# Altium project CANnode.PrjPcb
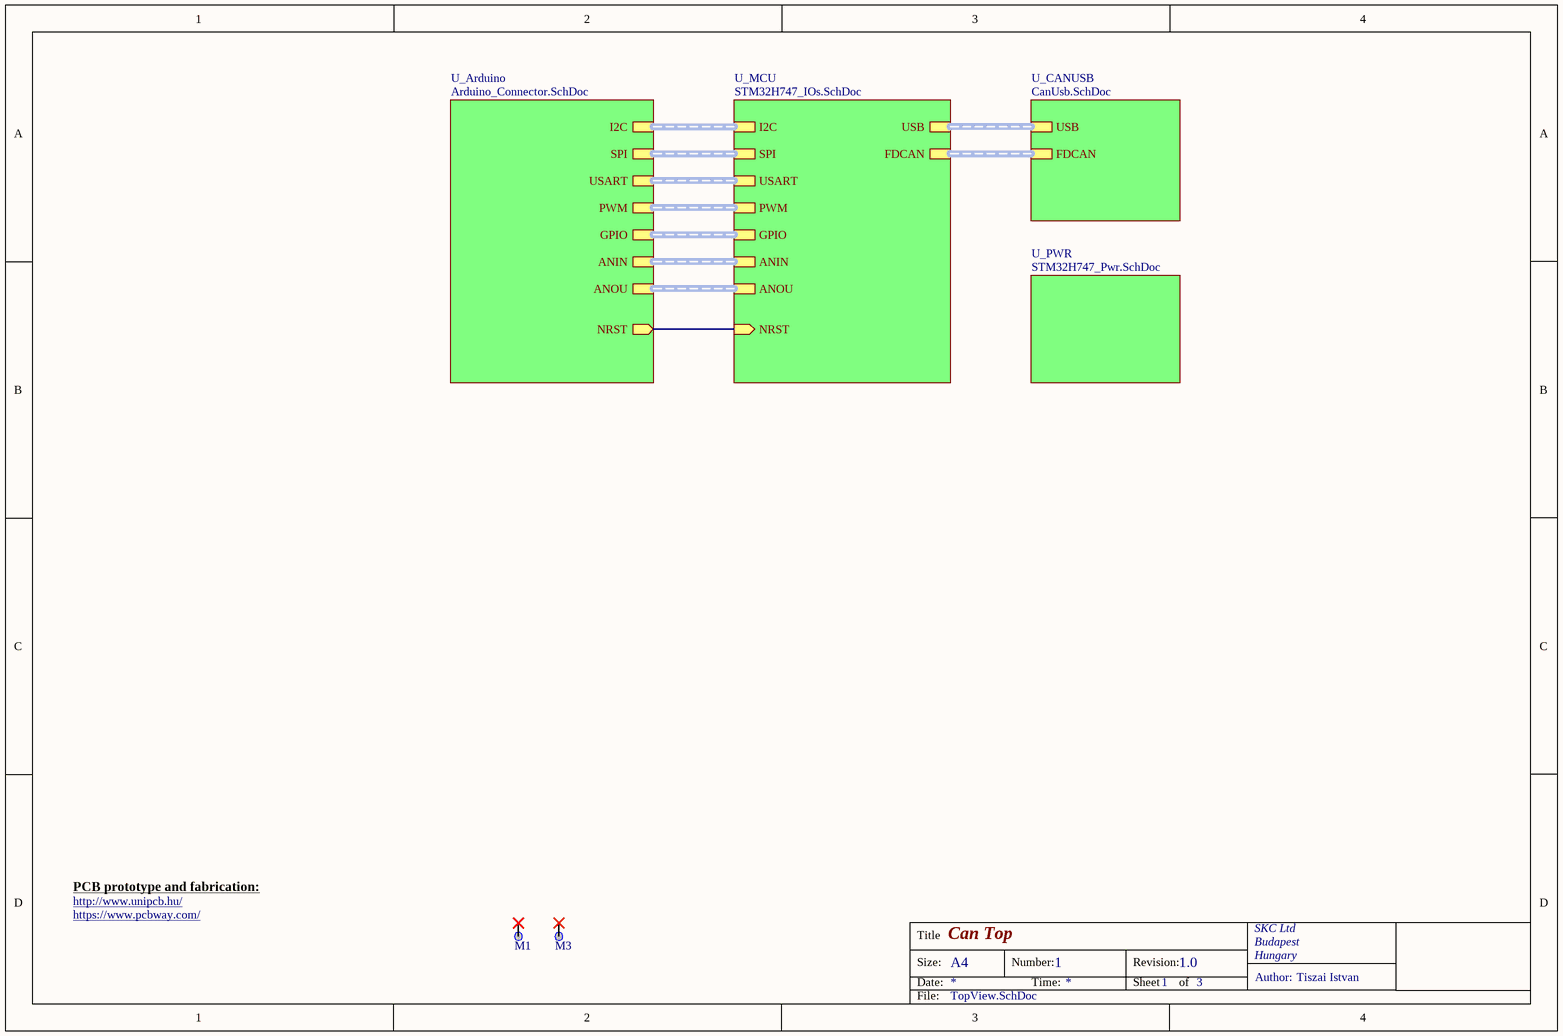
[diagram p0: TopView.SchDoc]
5 sheets, 99 parts. Net scope: hierarchical (ports join the sheet entries above them; power ports are global).
Board file: CANnode.PcbDoc
Sheets:
  TopView.SchDoc
    U_MCU = STM32H747_IOs.SchDoc
    U_PWR = STM32H747_Pwr.SchDoc
    U_CANUSB = CanUsb.SchDoc
    U_Arduino = Arduino_Connector.SchDoc

## Sheet TopView.SchDoc: Can Top
size A4; Author: Tiszai Istvan; Organization: SKC Ltd; Address1: Budapest; Address2: Hungary; DocumentNumber: 1; Revision: 1.0; SheetNumber: 1; SheetTotal: 3

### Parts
M1  (no value)  [Keystone 614]  (no BOM)
M3  (no value)  [Keystone 614]  (no BOM)

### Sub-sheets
U_Arduino = Arduino_Connector.SchDoc: I2C (harness I2C), SPI (harness SPI), USART (harness USART), PWM (harness PWM), GPIO (harness GPIO), ANIN (harness ANIN), ANOU (harness ANOU), NRST (out)
U_CANUSB = CanUsb.SchDoc: USB (harness USB), FDCAN (harness FDCAN)
U_MCU = STM32H747_IOs.SchDoc: NRST (in), USB (harness USB), FDCAN (harness FDCAN), I2C (harness I2C), SPI (harness SPI), USART (harness USART), PWM (harness PWM), GPIO (harness GPIO), ANIN (harness ANIN), ANOU (harness ANOU)
U_PWR = STM32H747_Pwr.SchDoc: no entries

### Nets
NRST: sheet U_MCU/NRST, sheet U_Arduino/NRST

Not connected (* = marked no-connect by the designer): M1 1*; M3 1*

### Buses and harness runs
harness sheet U_Arduino/ANIN = sheet U_MCU/ANIN
harness sheet U_Arduino/ANOU = sheet U_MCU/ANOU
harness sheet U_Arduino/GPIO = sheet U_MCU/GPIO
harness sheet U_Arduino/I2C = sheet U_MCU/I2C
harness sheet U_Arduino/PWM = sheet U_MCU/PWM
harness sheet U_Arduino/SPI = sheet U_MCU/SPI
harness sheet U_Arduino/USART = sheet U_MCU/USART
harness sheet U_CANUSB/FDCAN = sheet U_MCU/FDCAN
harness sheet U_CANUSB/USB = sheet U_MCU/USB

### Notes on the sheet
- http://www.unipcb.hu/
- https://www.pcbway.com/
- PCB prototype and fabrication:

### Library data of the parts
M1 M3 = TP: TAVTARTO

## Sheet STM32H747_IOs.SchDoc: Can STM32H747 IOs
size A4; Author: Tiszai Istvan; CompanyName: SKC Ltd; Engineer: Tiszai Istvan; Organization: SKC Ltd; Address1: Budapest; Address2: Hungary; DocumentNumber: 1; Revision: 1.0; SheetNumber: 2; SheetTotal: 3; FileName: STM32H747_IOs.SchDoc
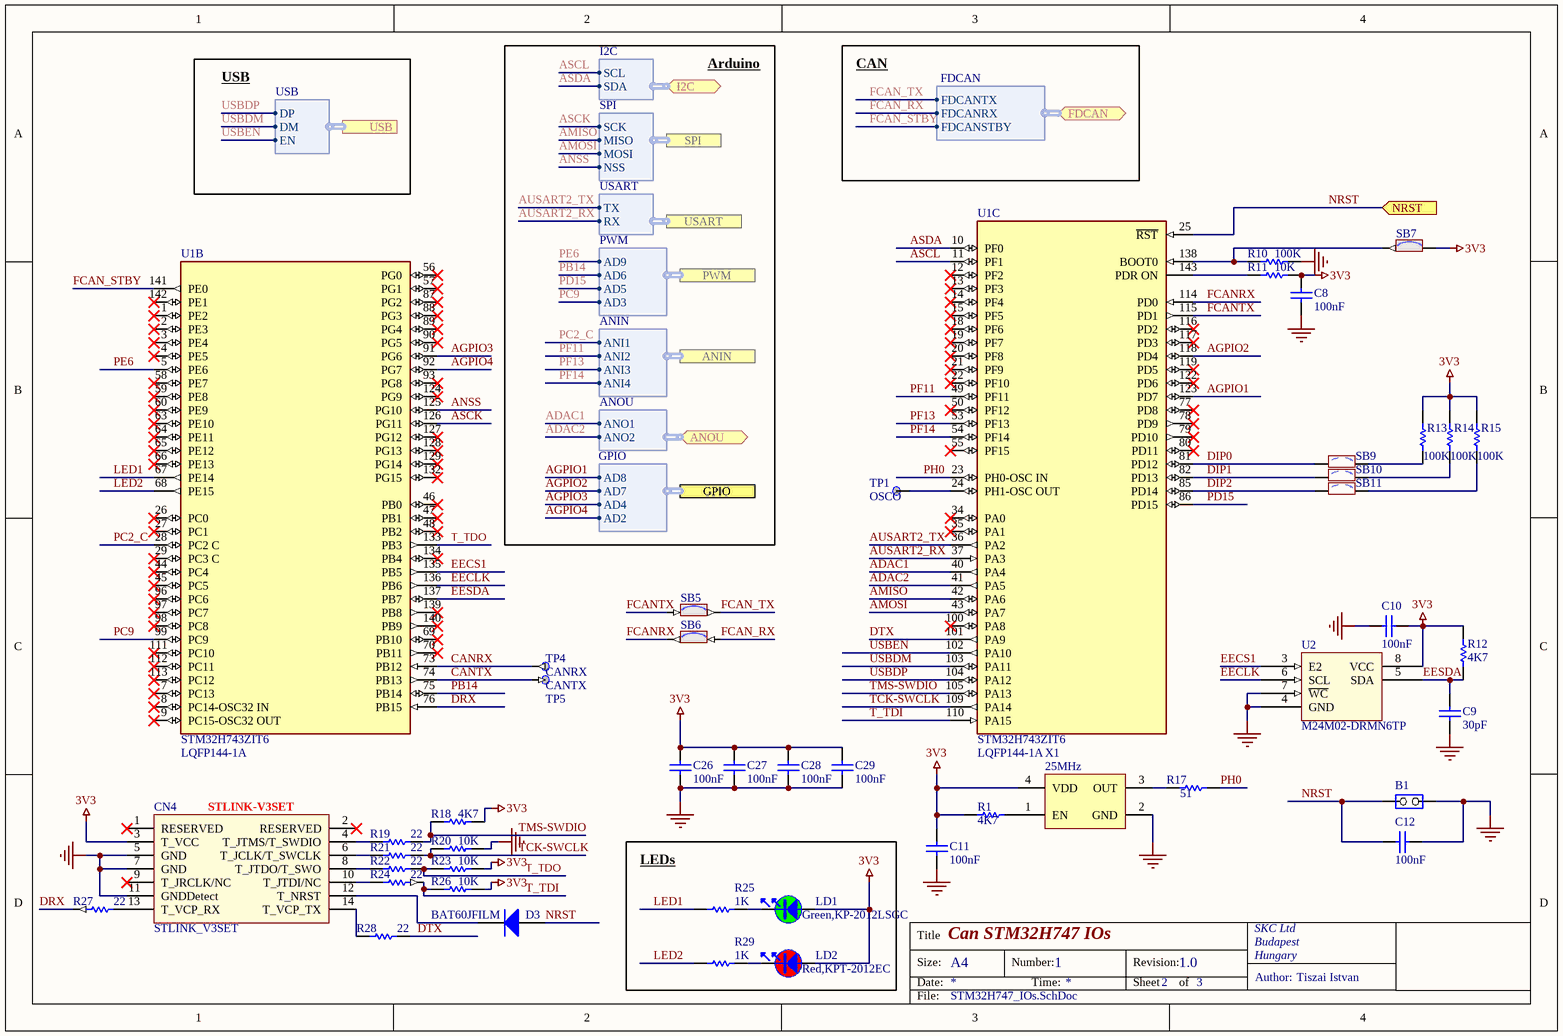
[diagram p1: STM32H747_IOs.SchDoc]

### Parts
B1  berg2  [SIP2/2.54]  (value not drawn)
C8  100nF  [0603]
C9  30pF  [0603]
C10  100nF  [0603]
C11  100nF  [0603]
C12  100nF  [0603]
C26  100nF  [0603]
C27  100nF  [0603]
C28  100nF  [0603]
C29  100nF  [0603]
CN4  STLINK_V3SET  [HDR2X7--50mil]
D3  BAT60JFILM  [SOD-323]
LD1  value Green,KP-2012LSGC  [LED 0805/2012 GREEN]  (hidden comment: LED_green)
LD2  value Red,KPT-2012EC  [LED 0805/2012 RED]  (hidden comment: LED_red)
R1  4K7  [0603]
R10  100K  [0603]
R11  10K  [0603]
R12  4K7  [0603]
R13  100K  [0603]
R14  100K  [0603]
R15  100K  [0603]
R17  value 51  [0603]  (hidden comment: 51R)
R18  4K7  [0603]
R19  22  [0603]
R20  10K  [0603]
R21  22  [0603]
R22  22  [0603]
R23  10K  [0603]
R24  22  [0603]
R25  1K  [0603]
R26  10K  [0603]
R27  22  [0603]
R28  22  [0603]
R29  1K  [0603]
SB5  SB_ON  [sb0603]  (value not drawn)
SB6  SB_ON  [sb0603]  (value not drawn)
SB7  SB_ON  [sb0603]  (value not drawn)
SB9  SB_OFF  [SB0603]  (value not drawn)
SB10  SB_OFF  [SB0603]  (value not drawn)
SB11  SB_OFF  [SB0603]  (value not drawn)
TP1  OSCO  [Through Hole Pad]
TP4  CANRX  [Through Hole Pad]
TP5  CANTX  [Through Hole Pad]
U1  STM32H743ZIT6  Package: LQFP144-1A  [FP-LQFP144-1A-IPC_B]  (parts B,C of 3)
U2  M24M02-DRMN6TP  [SOIC-8]
X1  value 25MHz  [OSC_NDK]  (hidden comment: Oscillator_4pins)

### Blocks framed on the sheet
LEDs: LD1 LD2 R25 R29

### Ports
ANIN (harness ANIN), ANOU (bidir, harness ANOU), FDCAN (bidir, harness FDCAN), GPIO (harness GPIO), I2C (bidir, harness I2C), NRST (in), PWM (harness PWM), SPI (harness SPI), USART (harness USART), USB (harness USB)

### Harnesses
FDCAN: FDCANTX, FDCANRX, FDCANSTBY
USB: EN, DM, DP
I2C: SCL, SDA
SPI: MISO, SCK, MOSI, NSS
USART: RX, TX
PWM: AD6, AD9, AD5, AD3
ANIN: ANI2, ANI1, ANI3, ANI4
ANOU: ANO1, ANO2
GPIO: AD7, AD8, AD4, AD2

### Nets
3V3: C8.2 C10.1 C11.2 C26.2 C27.2 C28.2 C29.2 CN4.3(T_VCC) LD1.1 LD2.1 R1.2 R11.1 R12.1 R13.1 R14.1 R15.1 R18.1 R23.1 R26.1 SB7.2 U2.8(VCC) X1.4(VDD)
GND: B1.1(COMMON) C8.1 C9.1 C10.2 C11.1 C12.1 C26.1 C27.1 C28.1 C29.1 CN4.5(GND) CN4.7(GND) CN4.11(GNDDetect) R10.1 R20.1 U2.4(GND) U2.7(~{WC}) X1.2(GND)
ADAC1: U1.40(PA4) ; port ANOU.ANO1
ADAC2: U1.41(PA5) ; port ANOU.ANO2
AGPIO1: U1.123(PD7) ; port GPIO.AD8
AGPIO2: U1.118(PD4) ; port GPIO.AD7
AGPIO3: U1.91(PG6) ; port GPIO.AD4
AGPIO4: U1.92(PG7) ; port GPIO.AD2
AMISO: U1.42(PA6) ; port SPI.MISO
AMOSI: U1.43(PA7) ; port SPI.MOSI
ANSS: U1.125(PG10) ; port SPI.NSS
ASCK: U1.126(PG11) ; port SPI.SCK
ASCL: U1.11(PF1) ; port I2C.SCL
ASDA: U1.10(PF0) ; port I2C.SDA
AUSART2_RX: U1.37(PA3) ; port USART.RX
AUSART2_TX: U1.36(PA2) ; port USART.TX
CANRX: TP4.1 U1.73(PB12)
CANTX: TP5.1 U1.74(PB13)
DIP0: SB9.1 U1.81(PD12)
DIP1: SB10.1 U1.82(PD13)
DIP2: SB11.1 U1.85(PD14)
DRX: R27.1 U1.76(PB15)
DTX: R28.2 U1.101(PA9)
EECLK: U1.136(PB6) U2.6(SCL)
EECS1: U1.135(PB5) U2.3(E2)
EESDA: C9.2 R12.2 U1.137(PB7) U2.5(SDA)
FCAN_RX: SB6.2 ; port FDCAN.FDCANRX
FCAN_STBY: U1.141(PE0) ; port FDCAN.FDCANSTBY
FCAN_TX: SB5.2 ; port FDCAN.FDCANTX
FCANRX: SB6.1 U1.114(PD0)
FCANTX: SB5.1 U1.115(PD1)
LED1: R25.1 U1.67(PE14)
LED2: R29.1 U1.68(PE15)
NRST: B1.2(NO) C12.2 D3.1(A) U1.25(~{RST}) ; port NRST
PB14: U1.75(PB14) ; port PWM.AD6
PC2_C: U1.28(PC2_C) ; port ANIN.ANI1
PC9: U1.99(PC9) ; port PWM.AD3
PD15: U1.86(PD15) ; port PWM.AD5
PE6: U1.5(PE6) ; port PWM.AD9
PF11: U1.49(PF11) ; port ANIN.ANI2
PF13: U1.53(PF13) ; port ANIN.ANI3
PF14: U1.54(PF14) ; port ANIN.ANI4
PH0: R17.2 U1.23(PH0-OSC_IN)
T_TDI: R24.2 R26.2 U1.110(PA15)
T_TDO: R22.2 R23.2 U1.133(PB3)
TCK-SWCLK: R20.2 R21.2 U1.109(PA14)
TMS-SWDIO: R18.2 R19.2 U1.105(PA13)
USBDM: U1.103(PA11) ; port USB.DM
USBDP: U1.104(PA12) ; port USB.DP
USBEN: U1.102(PA10) ; port USB.EN
NetCN4_4: CN4.4(T_JTMS/T_SWDIO) R19.1
NetCN4_6: CN4.6(T_JCLK/T_SWCLK) R21.1
NetCN4_8: CN4.8(T_JTDO/T_SWO) R22.1
NetCN4_10: CN4.10(T_JTDI/NC) R24.1
NetCN4_12: CN4.12(T_NRST) D3.2(K)
NetCN4_13: CN4.13(T_VCP_RX) R27.2
NetCN4_14: CN4.14(T_VCP_TX) R28.1
NetLD1_2: LD1.2 R25.2
NetLD2_2: LD2.2 R29.2
NetR1_1: R1.1 X1.1(EN)
NetR10_2: R10.2 SB7.1 U1.138(BOOT0)
NetR11_2: R11.2 U1.143(PDR_ON)
NetR13_2: R13.2 SB9.2
NetR14_2: R14.2 SB10.2
NetR15_2: R15.2 SB11.2
NetR17_1: R17.1 X1.3(OUT)
NetTP1_1: TP1.1 U1.24(PH1-OSC_OUT)

Not connected (* = marked no-connect by the designer): CN4 1(RESERVED)* 2(RESERVED)* 9(T_JRCLK/NC)*; U1 1(PE2)* 2(PE3)* 3(PE4)* 4(PE5)* 7(PC13)* 8(PC14-OSC32_IN)* 9(PC15-OSC32_OUT)* 12(PF2)* 13(PF3)* 14(PF4)* 15(PF5)* 18(PF6)* 19(PF7)* 20(PF8)* 21(PF9)* 22(PF10)* 26(PC0)* 27(PC1)* 29(PC3_C)* 34(PA0)* 35(PA1)* 44(PC4)* 45(PC5)* 46(PB0)* 47(PB1)* 48(PB2)* 50(PF12)* 55(PF15)* 56(PG0)* 57(PG1)* 58(PE7)* 59(PE8)* 60(PE9)* 63(PE10)* 64(PE11)* 65(PE12)* 66(PE13)* 69(PB10)* 70(PB11)* 77(PD8)* 78(PD9)* 79(PD10)* 80(PD11)* 87(PG2)* 88(PG3)* 89(PG4)* 90(PG5)* 93(PG8)* 96(PC6)* 97(PC7)* 98(PC8)* 100(PA8)* 111(PC10)* 112(PC11)* 113(PC12)* 116(PD2)* 117(PD3)* 119(PD5)* 122(PD6)* 124(PG9)* 127(PG12)* 128(PG13)* 129(PG14)* 132(PG15)* 134(PB4)* 139(PB8)* 140(PB9)* 142(PE1)*; U2 1(NC) 2(NC)

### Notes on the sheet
- USB
- Arduino
- CAN
- (near CN4) STLINK-V3SET

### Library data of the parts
B1 = JP2: berg 2 pin
C8 C10 C11 C26-C29 = MCD-00102: Capacitor, MLCC, 100nF, 25V, X7R, 10%, 0603
C9 = MCD-00102: Capacitor, MLCC, 30pF, 250V, 5%
C12 = CAP: Capacitor, MLCC, 100nF, 25V, X7R, 10%, 0603
CN4 = STLINK_V3SET: STLINK-V3SET -  Programmer / Debugger
D3 = Diode: Small Signal Schottky Diode, Single, 10 V, 3 A, 580 mV, 5 A
LD1 = MCD-00050: LED, Low Power, Green, SMD, 0805 2 mA,
LD2 = MCD-00049: LED, Low Power, High Efficiency Red, SMD, 0805 , 30 mA
R1 = MCD-00053: Resistor,,5%
R10 R12-R15 R18 R23 R26 = MCD-00053: Resistor,5%
R11 = MCD-00053: Resistor, 5%,
R17 = MCD-00485: Resistor,1%,
R19 = Resistor_ST: Resistor, 22, 1%
R20 = MCD-00053: Resistor,10K,5%
R21 R22 R24 R27 R28 = Resistor_ST: Resistor 22, 1%
R25 = MCD-00225: Resistor,1K,1%
R29 = MCD-00507: Resistor,1K,1%,
SB5-SB7 = MCD-00071: Solder Bridge ON; Part_Type: Mechanical; Provided_By: Subcon; Initial_Board_Reference: mb1274
SB9-SB11 = MCD-00072: Solder Bridge OFF; Part_Type: Mechanical; Initial_Board_Reference: mb1274
TP1 TP4 TP5 = TP
U1 = CMP-12105-000003-1: IC MCU 32BIT 2MB FLASH 144LQFP; Manufacturer: STMicroelectronics; Number Of I2C Channels: 4; Number Of A/D Converters: 2; Standoff Height: 0.05mm; Interface: I2C,SPI,UART,USART,EBI/EMI,CAN,USB,LIN,IrDA,Other; Max Supply Voltage: 3.6V; Number Of Adc Channels: 36; Ram Size: 1MBytes; Number Of Cores: 1; Frequency: 400MHz; Data Bus Width: 32bits; Core Architecture: ARM Cortex-M7; Memory Size: 2MBytes; Number Of Timers/Counters: 22; Min Supply Voltage: 1.62V; Number Of Spi Channels: 6; Max Junction Temp: +125°C; Number Of I/Os: 114
U2 = M24M02-DRMN6TP: 2-Mbit serial I²C bus EEPROM
X1 = MCD-00597: Oscillator, 25 MHz, 50 ppm, SMD, 3.2mm x 2.5mm, CMOS, 3.3 V

## Sheet STM32H747_Pwr.SchDoc: Can STM32H747 Power
size A4; Author: Tiszai Istvan; CompanyName: SKC Ltd; Organization: GreenLab Ltd; Address1: Budapest; Address2: Hungary; DocumentNumber: 1; Revision: 1.0; SheetNumber: 3; SheetTotal: 3
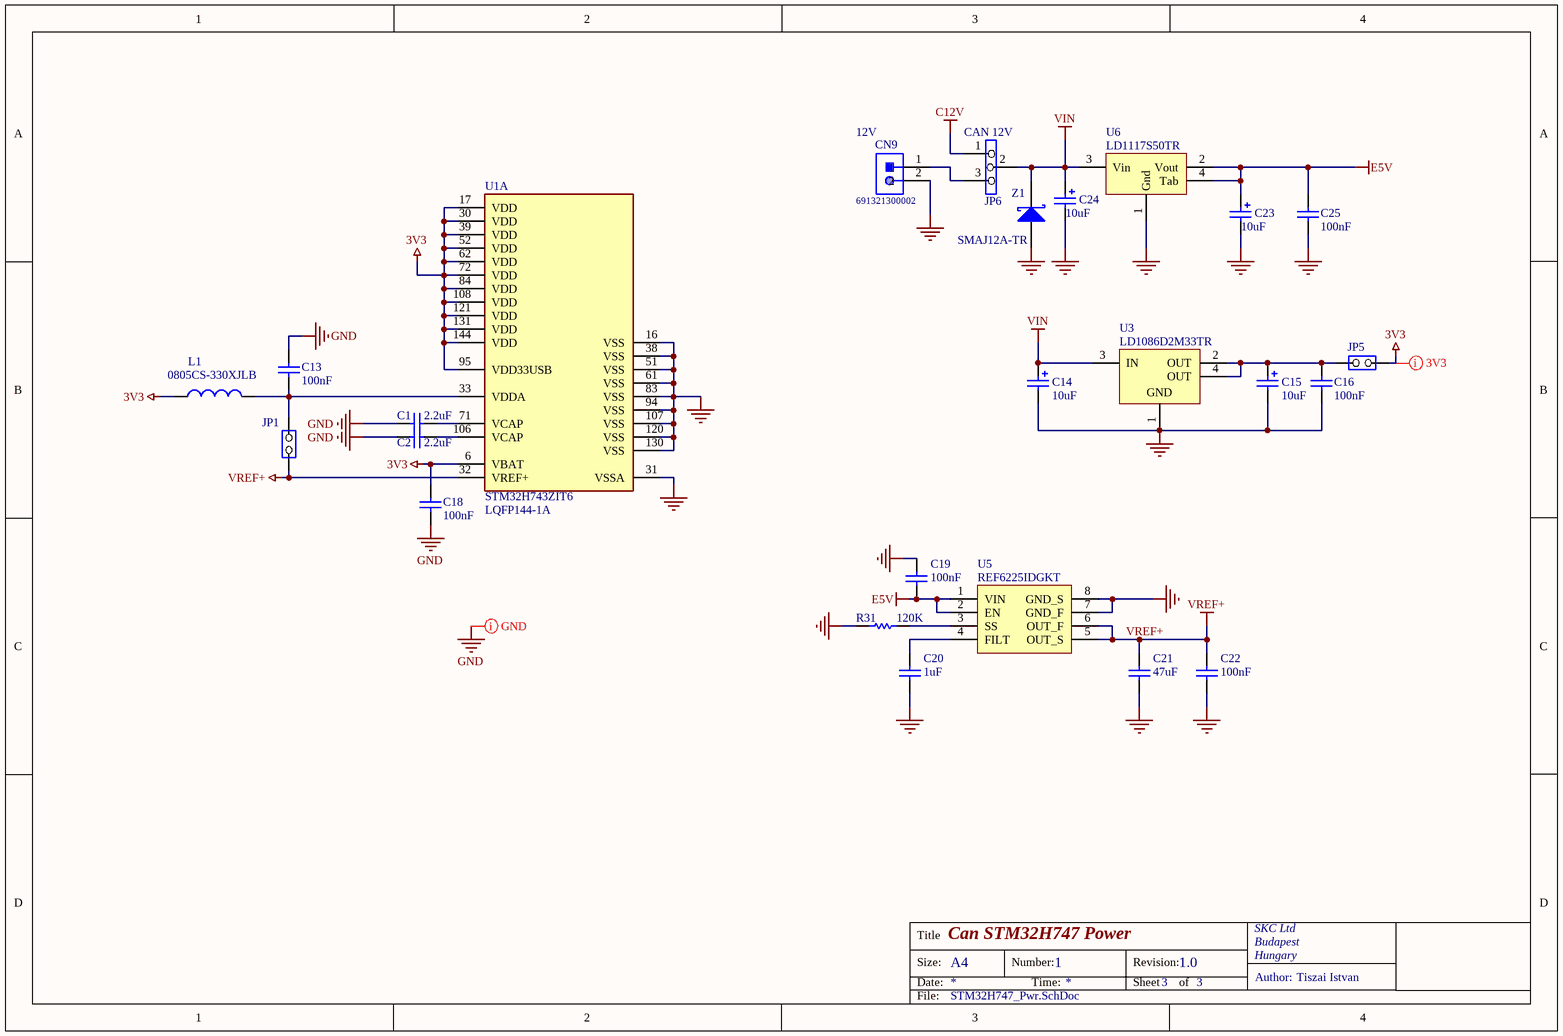
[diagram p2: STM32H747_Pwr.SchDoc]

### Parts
C1  2.2uF  [TAN-A]
C2  2.2uF  [TAN-A]
C13  100nF  [0603]
C14  10uF  [0805]
C15  10uF  [0805]
C16  100nF  [0603C]
C18  100nF  [0603]
C19  100nF  [0603]
C20  1uF  [0805]
C21  47uF  [0805]
C22  100nF  [0603C]
C23  10uF  [0805]
C24  10uF  [0805]
C25  100nF  [0603C]
CN9  691321300002  [691305330002]
JP1  (no value)  [SIP2/2.54]
JP5  (no value)  [SIP2/2.54]
JP6  (no value)  [SIP3]
L1  Manufacturer_Part_Number: 0805CS-330XJLB  [0805]  (hidden comment: BEAD)
R31  120K  [0603]
U1  STM32H743ZIT6  Package: LQFP144-1A  [FP-LQFP144-1A-IPC_B]  (part A of 3)
U3  LD1086D2M33TR  [D2PAK_A_M]
U5  REF6225IDGKT  [SSOP8]
U6  LD1117S50TR  [sot223]
Z1  SMAJ12A-TR  [SMB]

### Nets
3V3: C18.2 JP5.1(COMMON) L1.1 U1.6(VBAT) U1.17(VDD) U1.30(VDD) U1.39(VDD) U1.52(VDD) U1.62(VDD) U1.72(VDD) U1.84(VDD) U1.95(VDD33USB) U1.108(VDD) U1.121(VDD) U1.131(VDD) U1.144(VDD)
C12V: JP6.1
E5V: C19.2 C23.1 C25.1 U5.1(VIN) U5.2(EN) U6.2(Vout) U6.4(Tab)
GND: C1.2 C2.2 C13.2 C14.2 C15.2 C16.2 C18.1 C19.1 C20.2 C21.2 C22.2 C23.2 C24.2 C25.2 CN9.2 R31.1 U1.16(VSS) U1.31(VSSA) U1.38(VSS) U1.51(VSS) U1.61(VSS) U1.83(VSS) U1.94(VSS) U1.107(VSS) U1.120(VSS) U1.130(VSS) U3.1(GND) U5.7(GND_F) U5.8(GND_S) U6.1(Gnd) Z1.1(A)
VIN: C14.1 C24.1 JP6.2 U3.3(IN) U6.3(Vin) Z1.2(K)
VREF+: C21.1 C22.1 JP1.1(COMMON) U1.32(VREF+) U5.5(OUT_S) U5.6(OUT_F)
NetC1_1: C1.1 U1.71(VCAP)
NetC2_1: C2.1 U1.106(VCAP)
NetC13_1: C13.1 JP1.2(NO) L1.2 U1.33(VDDA)
NetC15_1: C15.1 C16.1 JP5.2(NO) U3.2(OUT) U3.4(OUT)
NetC20_1: C20.1 U5.4(FILT)
NetCN9_1: CN9.1 JP6.3
NetR31_2: R31.2 U5.3(SS)

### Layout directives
net class GND: GND
net class 3V3: 3V3

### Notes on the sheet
- (near CN9) 12V
- (near JP6) CAN 12V
- Labels drawn without touching a wire or pin: GND

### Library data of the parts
C1 C2 = Cap_2.2uF_X7R_10%_0805: Capacitor,2.2uF,Tantalum,16V,10%
C13 C18 = MCD-00102: Capacitor, MLCC, 100nF, 25V, X7R, 10%
C14 = Cap Pol1: SMD Multilayer Ceramic Capacitor, 10 µF, 25 V,10%
C15 C23 C24 = Cap Pol1: SMD Multilayer Ceramic Capacitor, 10 µF, 25 V, 10%
C16 = Cap: Capacitor, MLCC, 100nF, 25V, X7R, 10%,
C19 C22 C25 = Cap: Capacitor, MLCC, 100nF, 25V, X7R, 10%
C20 = Cap: Capacitor, MCC 1uF, 10V, 10%
C21 = Cap: SMD Multilayer Ceramic Capacitor, 47 µF, 6.3 V,20%
CN9 = 691321300002: Serie 321 - 3.81mm Vertical PCB Header WR-TBL, 2 pin
JP1 JP5 = JP2: berg 2 pin
JP6 = Jumper3: berg 3 pin
L1 = MCD-00047: SMD Chip ferrite bead, 0.27R@250MHz +/-25%, 500mA, 0805; Manufacturer: COILCRAFT; Value: 0.27@250MHz
R31 = MCD-00166: Resistor,120K,1%
U1 = CMP-12105-000003-1: as U1 on sheet STM32H747_IOs
U3 = CMP-0244-00505-1: 1.5A, Low Drop Positive Voltage Regulator, 3.3V, 4-Pin D2PAK/A, Tape and Reel
U5 = MCD-01138: IC VREF SERIES 2.5V 8VSSOP
U6 = MCD-00088: IC REG LDO 5V 0.8A SOT223
Z1 = D Schottky: Schottky Diode,SMAJ1 Series, Unidirectional, 12 V, 25.3 V

## Sheet CanUsb.SchDoc: Can & Usb Interface
size A4; Author: Tiszai Istvan; Organization: SKC Ltd; Address1: Budapest; Address2: Hungary; DocumentNumber: 1; Revision: 1.0; SheetNumber: 4; SheetTotal: 4
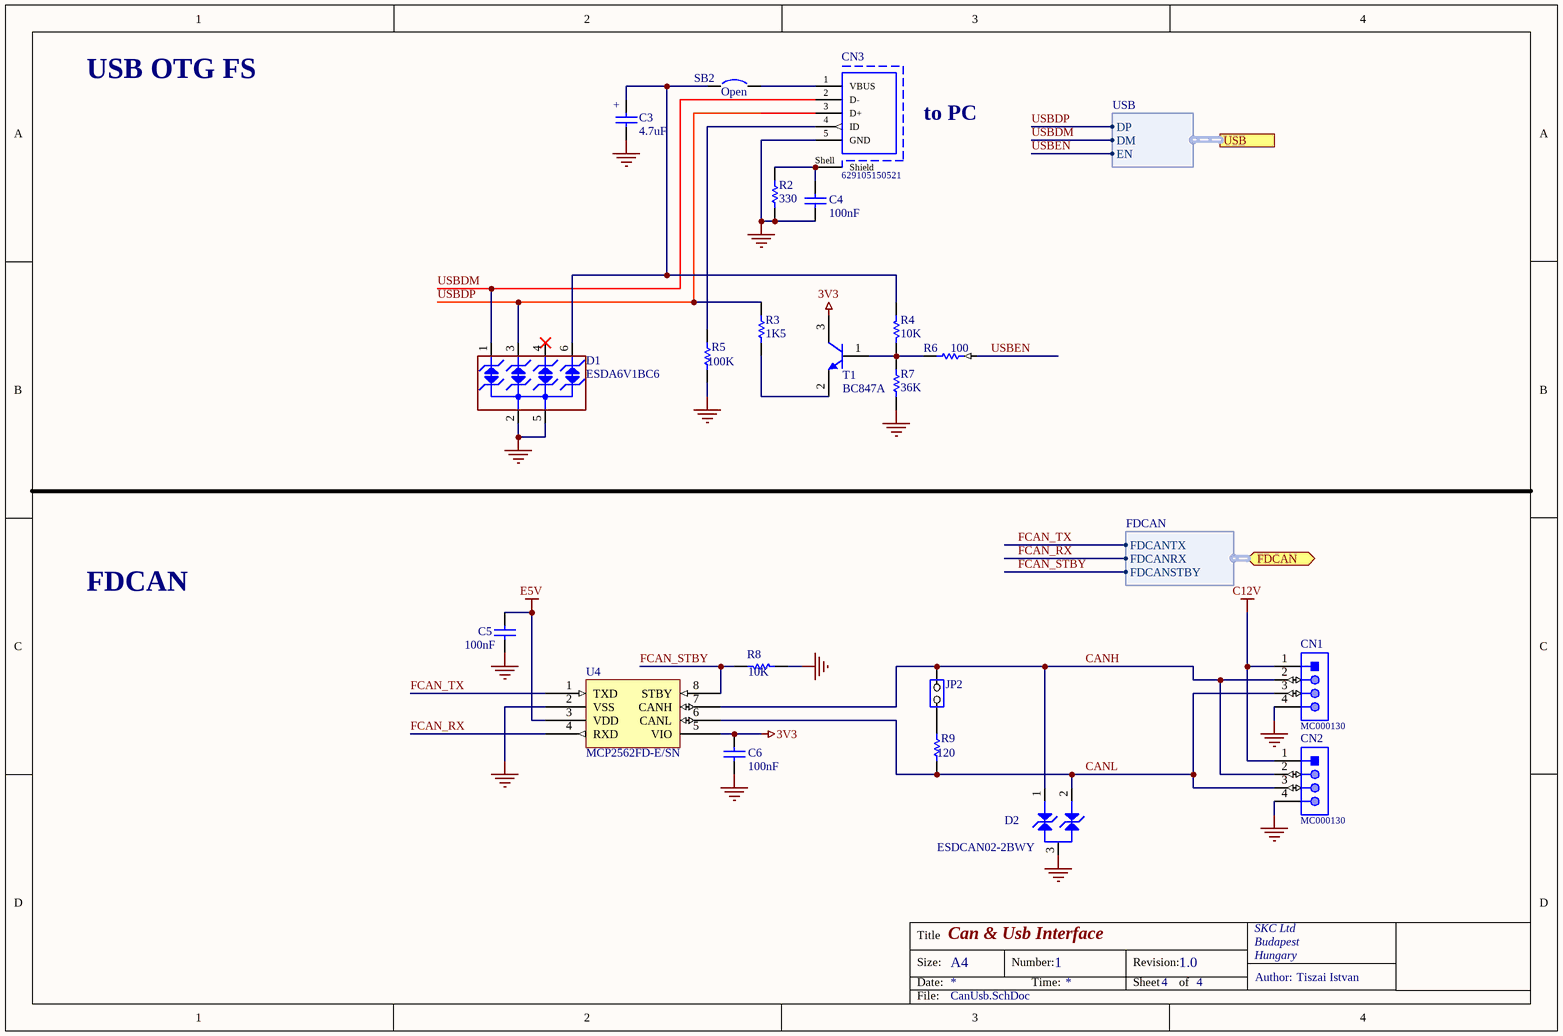
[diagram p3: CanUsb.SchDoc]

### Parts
C3  4.7uF  [TAN-A]
C4  100nF  [0603]
C5  100nF  [0603]
C6  100nF  [0603]
CN1  MC000130  [691305330004]
CN2  MC000130  [691305330004]
CN3  629105150521  [USB_micro_629105150521]
D1  ESDA6V1BC6  [SOT23-6-L]
D2  ESDCAN02-2BWY  [DIO_SOT323]
JP2  (no value)  [SIP2/2.54]
R2  330  [0603]
R3  1K5  [0603]
R4  10K  [0603]
R5  100K  [0603]
R6  100  [0603]
R7  36K  [0603]
R8  10K  [0603]
R9  120  [0805]
SB2  Open  [SB0603]
T1  BC847A  [SOT-23]
U4  MCP2562FD-E/SN  [SOIC-8]

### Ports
FDCAN (bidir, harness FDCAN), USB (harness USB)

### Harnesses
USB: DP, DM, EN
FDCAN: FDCANTX, FDCANRX, FDCANSTBY

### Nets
3V3: C6.1 T1.3(C) U4.5(VIO)
C12V: CN1.1 CN2.1
E5V: C5.1 U4.3(VDD)
GND: C3.2 C4.2 C5.2 C6.2 CN1.4 CN2.4 CN3.5(GND) D1.2(IO2) D1.5(IO4) D2.3 R2.2 R5.2 R7.1 R8.2 U4.2(VSS)
CANH: CN1.2 CN2.2 D2.1 JP2.1(COMMON) U4.7(CANH)
CANL: CN1.3 CN2.3 D2.2 R9.2 U4.6(CANL)
FCAN_RX: U4.4(RXD) ; port FDCAN.FDCANRX
FCAN_STBY: R8.1 U4.8(STBY) ; port FDCAN.FDCANSTBY
FCAN_TX: U4.1(TXD) ; port FDCAN.FDCANTX
USBDM: CN3.2(D-) D1.1(IO1) ; port USB.DM
USBDP: CN3.3(D+) D1.3(GND) R3.1 ; port USB.DP
USBEN: R6.2 ; port USB.EN
NetC3_1: C3.1 D1.6(NC) R4.1 SB2.1
NetC4_1: C4.1 CN3.Shell(Shield) R2.1
NetCN3_1: CN3.1(VBUS) SB2.2
NetCN3_4: CN3.4(ID) R5.1
NetJP2_2: JP2.2(NO) R9.1
NetR3_2: R3.2 T1.2(E)
NetR4_2: R4.2 R6.1 R7.2 T1.1(B)

Not connected (* = marked no-connect by the designer): D1 4(IO3)*

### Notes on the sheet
- USB OTG FS
- (near C3) +
- to PC
- FDCAN

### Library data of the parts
C3 = CAP SMD 0603  X5R 1µF 25V 10%: 4.7 uf, Tantalum, 16V 10%; Value: 4.7µF
C4-C6 = Cap: Capacitor, MLCC, 100nF, 25V, X7R, 10%, 0603
CN1 CN2 = 691305340004: Serie 3053 - 3.81mm Horizontal PCB Header with Plastic Latch WR-TBL, 4 pin
CN3 = 629105150521: Micro USB 2.0 Type B Receptacle WR-COM, Horizontal, SMT, with Pegs, High Current at Pin 1 & Pin 5
D1 = ESDA6V1BC6: 4-line ESD protection
D2 = ESDCAN02-2BWY: ESD Suppressor TVS ±30kV 3-Pin SOT-323 T/R
JP2 = JP2: berg 2 pin
R2 = Resistor_ST: Resistor 330, 5%
R3 = Resistor_ST: Resistor 1k5, 5%
R4 R8 = Res1: Resistor 10K,5%
R5 = Resistor_ST: Resistor 100K, 5%
R6 = Resistor_ST: Resistor 100,5%
R7 = Res1: Resistor 36k, 1%
R9 = Resistor_ST: Resistor  120, 1%
SB2 = Circuit Breaker
T1 = NPN: NPN Bipolar Transistor
U4 = MCP2562FD: CAN Flexible Data Rate Transceiver

## Sheet Arduino_Connector.SchDoc: Can Arduino Connector
size A4; Author: Tiszai Istvan; Organization: GreenLab Ltd; Address1: Budapest; Address2: Hungary; DocumentNumber: 1; Revision: 1.0; SheetNumber: 5; SheetTotal: 5
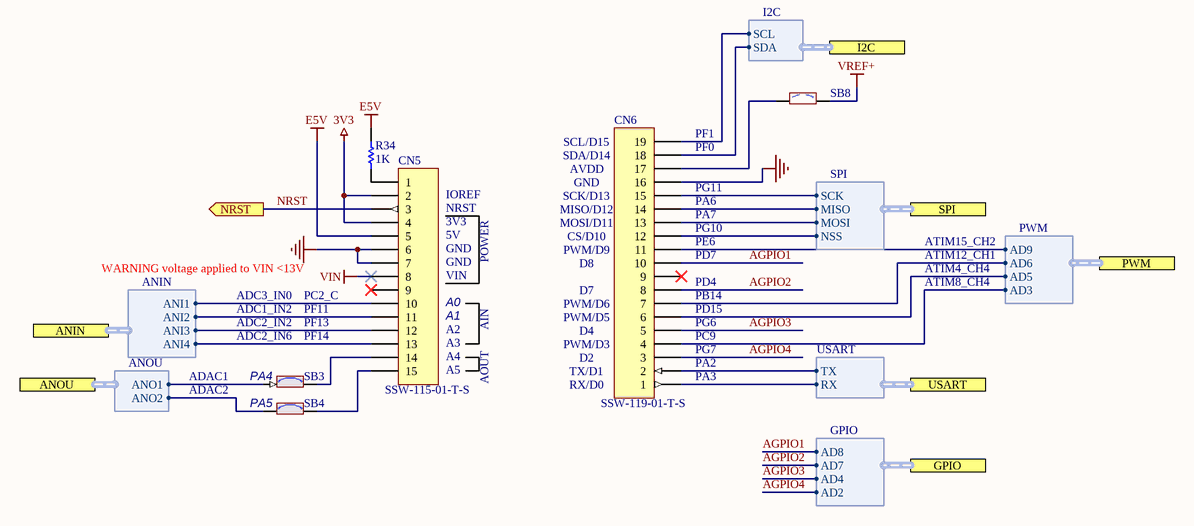
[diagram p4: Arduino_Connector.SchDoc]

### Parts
CN5  SSW-115-01-T-S  [SIP15]
CN6  SSW-119-01-T-S  [sip19]
R34  1K  [0603]
SB3  SB_ON  [sb0603]  (value not drawn)
SB4  SB_ON  [SB0603]  (value not drawn)
SB8  SB_OFF  [SB0603]  (value not drawn)

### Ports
ANIN (harness ANIN), ANOU (harness ANOU), GPIO (harness GPIO), I2C (harness I2C), NRST (out), PWM (harness PWM), SPI (harness SPI), USART (harness USART)

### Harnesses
I2C: SDA, SCL
SPI: MISO, SCK, MOSI, NSS
USART: RX, TX
PWM: AD6, AD9, AD5, AD3
GPIO: AD7, AD8, AD4, AD2
ANIN: ANI1, ANI2, ANI3, ANI4
ANOU: ANO1, ANO2

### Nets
3V3: CN5.2 CN5.4
E5V: CN5.5 R34.2
GND: CN5.6 CN5.7 CN6.16
VIN: CN5.8
VREF+: SB8.2
ADAC1: SB3.1 ; port ANOU.ANO1
ADAC2: SB4.1 ; port ANOU.ANO2
AGPIO1: CN6.10 ; port GPIO.AD8
AGPIO2: CN6.8 ; port GPIO.AD7
AGPIO3: CN6.5 ; port GPIO.AD4
AGPIO4: CN6.3 ; port GPIO.AD2
AMISO: CN6.14 ; port SPI.MISO
AMOSI: CN6.13 ; port SPI.MOSI
ANSS: CN6.12 ; port SPI.NSS
ASCK: CN6.15 ; port SPI.SCK
ASCL: CN6.19 ; port I2C.SCL
ASDA: CN6.18 ; port I2C.SDA
AUSART2_RX: CN6.1 ; port USART.RX
AUSART2_TX: CN6.2 ; port USART.TX
NRST: CN5.3 ; port NRST
PB14: CN6.7 ; port PWM.AD6
PC2_C: CN5.10 ; port ANIN.ANI1
PC9: CN6.4 ; port PWM.AD3
PD15: CN6.6 ; port PWM.AD5
PE6: CN6.11 ; port PWM.AD9
PF11: CN5.11 ; port ANIN.ANI2
PF13: CN5.12 ; port ANIN.ANI3
PF14: CN5.13 ; port ANIN.ANI4
NetCN5_1: CN5.1 R34.1
NetCN5_14: CN5.14 SB3.2
NetCN5_15: CN5.15 SB4.2
NetCN6_17: CN6.17 SB8.1

Not connected (* = marked no-connect by the designer): CN5 9*; CN6 9*

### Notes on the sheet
- (near CN6) SDA/D14
- (near CN6) SCL/D15
- AVDD
- (near CN6) PF1
- (near CN6) PF0
- (near CN5) IOREF
- (near CN5) NRST
- (near CN5) 3V3
- (near CN6) CS/D10
- (near CN6) SCK/D13
- (near CN6) MISO/D12
- (near CN6) MOSI/D11
- GND
- (near CN6) PG10
- (near CN6) PA7
- (near CN6) PA6
- (near CN6) PG11
- WARNING voltage applied to VIN <13V
- ADC3_IN0
- PC2_C
- (near CN5) A0
- (near CN5) 5V
- (near CN5) GND
- (near CN5) VIN
- POWER
- (near CN6) PWM/D6
- D7
- D8
- (near CN6) PWM/D9
- (near CN6) PB14
- (near CN6) PD4
- (near CN6) PD7
- (near CN6) PE6
- ATIM4_CH4
- ATIM8_CH4
- ATIM15_CH2
- ATIM12_CH1
- (near SB3) ADC2_IN6
- ADC2_IN2
- ADC1_IN2
- PF11
- PF13
- (near SB3) PF14
- (near CN5) A1
- (near CN5) A2
- (near CN5) A3
- (near CN5) A4
- AIN
- (near CN6) TX/D1
- D2
- D4
- (near CN6) PWM/D3
- (near CN6) PWM/D5
- (near CN6) PA2
- (near CN6) PG7
- (near CN6) PG6
- (near CN6) PD15
- (near CN6) PC9
- ADAC1
- ADAC2
- (near SB3) PA4
- PA5
- (near CN5) A5
- AOUT
- (near CN6) RX/D0
- (near CN6) PA3

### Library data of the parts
CN5 = MHDR1X15: Header, 15-Pin; Manufacturer: SAMTEC
CN6 = MHDR1X19: Header, 19-Pin; Manufacturer: SAMTEC
R34 = MCD-00225: Resistor,1K,1%
SB3 SB4 = MCD-00071: as SB5 on sheet STM32H747_IOs
SB8 = MCD-00072: as SB9 on sheet STM32H747_IOs

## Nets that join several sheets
3V3: STM32H747_IOs (22 pins), STM32H747_Pwr (16 pins), CanUsb (C6.1 T1.3 U4.5), Arduino_Connector (CN5.2 CN5.4)
C12V: STM32H747_Pwr (JP6.1), CanUsb (CN1.1 CN2.1)
E5V: STM32H747_Pwr (7 pins), CanUsb (C5.1 U4.3), Arduino_Connector (CN5.5 R34.2)
GND: STM32H747_IOs (18 pins), STM32H747_Pwr (31 pins), CanUsb (15 pins), Arduino_Connector (CN5.6 CN5.7 CN6.16)
VIN: STM32H747_Pwr (6 pins), Arduino_Connector (CN5.8)
VREF+: STM32H747_Pwr (6 pins), Arduino_Connector (SB8.2)
ADAC1: STM32H747_IOs (U1.40), Arduino_Connector (SB3.1)
ADAC2: STM32H747_IOs (U1.41), Arduino_Connector (SB4.1)
AGPIO1: STM32H747_IOs (U1.123), Arduino_Connector (CN6.10)
AGPIO2: STM32H747_IOs (U1.118), Arduino_Connector (CN6.8)
AGPIO3: STM32H747_IOs (U1.91), Arduino_Connector (CN6.5)
AGPIO4: STM32H747_IOs (U1.92), Arduino_Connector (CN6.3)
AMISO: STM32H747_IOs (U1.42), Arduino_Connector (CN6.14)
AMOSI: STM32H747_IOs (U1.43), Arduino_Connector (CN6.13)
ANSS: STM32H747_IOs (U1.125), Arduino_Connector (CN6.12)
ASCK: STM32H747_IOs (U1.126), Arduino_Connector (CN6.15)
ASCL: STM32H747_IOs (U1.11), Arduino_Connector (CN6.19)
ASDA: STM32H747_IOs (U1.10), Arduino_Connector (CN6.18)
AUSART2_RX: STM32H747_IOs (U1.37), Arduino_Connector (CN6.1)
AUSART2_TX: STM32H747_IOs (U1.36), Arduino_Connector (CN6.2)
FCAN_RX: STM32H747_IOs (SB6.2), CanUsb (U4.4)
FCAN_STBY: STM32H747_IOs (U1.141), CanUsb (R8.1 U4.8)
FCAN_TX: STM32H747_IOs (SB5.2), CanUsb (U4.1)
NRST: STM32H747_IOs (B1.2 C12.2 D3.1 U1.25), Arduino_Connector (CN5.3)
PB14: STM32H747_IOs (U1.75), Arduino_Connector (CN6.7)
PC2_C: STM32H747_IOs (U1.28), Arduino_Connector (CN5.10)
PC9: STM32H747_IOs (U1.99), Arduino_Connector (CN6.4)
PD15: STM32H747_IOs (U1.86), Arduino_Connector (CN6.6)
PE6: STM32H747_IOs (U1.5), Arduino_Connector (CN6.11)
PF11: STM32H747_IOs (U1.49), Arduino_Connector (CN5.11)
PF13: STM32H747_IOs (U1.53), Arduino_Connector (CN5.12)
PF14: STM32H747_IOs (U1.54), Arduino_Connector (CN5.13)
USBDM: STM32H747_IOs (U1.103), CanUsb (CN3.2 D1.1)
USBDP: STM32H747_IOs (U1.104), CanUsb (CN3.3 D1.3 R3.1)
USBEN: STM32H747_IOs (U1.102), CanUsb (R6.2)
